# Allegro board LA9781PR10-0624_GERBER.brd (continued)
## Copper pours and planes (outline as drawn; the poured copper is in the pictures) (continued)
LX_CHG on BOTTOM (solid shape): 215.24,29.4 215.24,26.48 216.38,25.34 216.38,23.05 215.62,22.29 215.62,20.38 215.24,20 213.46,20 212.06,21.4 205.84,21.4 205.33,21.91 205.33,28.55 205.76,28.98 211.92,28.98 212.6,29.66 214.98,29.66
LX_CHG on BOTTOM (solid shape): 224.26,30.16 224.26,29.53 224.13,29.4 223.75,29.4 223.62,29.27 223.62,28.64 223.49,28.51 222.48,28.51 222.35,28.64 222.35,30.16 222.48,30.29 224.13,30.29
LX_CHG on IN2 (solid shape): 223.62,28.89 223.62,28.26 223.37,28 221.08,28 221.08,29.15 223.37,29.15
LX_CHG on IN2 (solid shape): 215.87,27.12 215.87,25.72 215.62,25.46 213.97,25.46 213.71,25.72 213.71,27.12 214.1,27.5 215.49,27.5
P1_SW on TOP (solid shape): 172.19,158.94 172.19,157.8 172.44,157.54 174.47,157.54 174.73,157.8 174.73,158.94 175.11,159.32 178.15,159.32 178.66,158.81 178.66,155.08 178.46,154.88 175.67,154.88 175.06,154.27 174.37,154.27 174.22,154.42 174.22,154.75 174.09,154.88 173.46,154.88 173.2,154.62 173.2,153.86 172.95,153.61 170.15,153.61 169.77,153.99 169.77,155.51 169.39,155.89 167.99,155.89 167.74,156.15 167.74,157.29 167.99,157.54 168.38,157.54 168.63,157.8 168.63,159.07 168.88,159.32 171.8,159.32
P2_SW on TOP (solid shape): 184.63,158.94 184.63,157.8 184.89,157.54 186.92,157.54 187.17,157.8 187.17,159.07 187.3,159.2 190.6,159.2 190.73,159.07 190.73,155.16 190.47,154.9 185.39,154.9 185.14,154.65 185.14,154.27 184.91,154.04 184.5,154.04 184.38,154.17 184.38,154.75 183.62,154.75 183.62,153.86 183.36,153.61 182.47,153.61 182.09,153.99 182.09,154.62 181.2,155.51 181.2,159.07 181.33,159.2 184.38,159.2
P2_SW on BOTTOM (solid shape): 187.81,158.69 187.81,157.8 187.68,157.67 186.66,157.67 186.54,157.54 186.54,156.91 186.41,156.78 186.03,156.78 185.9,156.91 185.9,158.05 185.97,158.19 185.97,158.35 185.97,158.37 186.41,158.81 187.68,158.81
P3_SW on TOP (solid shape): 198.73,158.81 198.73,157.42 198.98,157.16 201.01,157.16 201.27,157.42 201.27,158.81 201.4,158.94 204.57,158.94 204.82,158.69 204.82,154.24 204.19,153.61 196.95,153.61 196.7,153.86 196.7,154.83 196.49,155.03 194.97,155.03 194.79,154.85 194.79,153.86 194.54,153.61 193.9,153.61 193.65,153.86 193.65,154.75 192.76,154.75 192.76,153.86 192.51,153.61 191.74,153.61 191.49,153.86 191.49,156.91 191.87,157.29 194.92,157.29 195.17,157.54 195.17,158.69 195.43,158.94 198.6,158.94
P3_SW on BOTTOM (solid shape): 197.84,155.89 197.84,154.62 197.71,154.5 197.36,154.5 197.36,154.63 197.18,155.07 196.71,155.28 196.7,155.32 196.7,155.89 196.82,156.02 197.71,156.02
PBATT+ on TOP (solid shape): 189.46,15.69 189.46,6.54 189.2,6.29 185.41,6.29 185.16,6.53 185.16,10.72 185.38,10.94 186.4,10.94 187.04,11.58 187.04,12.64 186.92,12.76 185.01,12.76 184.76,13.02 184.76,15.94 185.01,16.19 188.95,16.19
PBATT+ on BOTTOM (solid shape): 192.63,15.43 192.63,11.49 190.98,9.84 186.28,9.84 185.77,10.35 185.77,13.78 186.28,14.29 187.3,14.29 187.55,14.03 188.06,14.03 188.31,14.29 188.31,15.56 188.82,16.07 192,16.07
PBATT+_C on TOP (solid shape): 193.78,10.61 193.78,9.72 193.52,9.46 193.52,8.02 193.48,7.93 193.39,7.92 192.94,7.76 193,7.29 193.14,7.14 193.14,6.92 193.27,6.8 193.27,3.58 193.22,3.57 192.41,2.65 193.22,1.73 193.27,1.72 193.27,1.59 193.01,1.33 188.57,1.33 188.19,1.72 188.19,4.26 190.22,6.29 190.22,10.61 190.6,10.99 193.39,10.99
PBATT+_C on BOTTOM (solid shape): 194.03,10.86 194.03,8.7 193.27,7.94 193.25,7.94 193,7.83 192.89,7.58 192.89,7.56 192.38,7.05 192.38,2.1 192,1.72 188.82,1.72 188.31,2.22 188.31,6.92 192.63,11.24 193.65,11.24
PBATT_IN_SS on BOTTOM (solid shape): 188.51,27.05 188.54,26.98 188.57,26.94 188.57,21.78 188.82,21.53 192.38,21.53 192.89,21.02 192.89,19.92 192.82,19.83 192.71,19.85 192.05,19.6 192.71,19.34 192.82,19.36 192.89,19.27 192.89,17.59 191.87,16.57 187.48,16.57 187.4,16.6 187.38,16.68 187.02,17.03 186.66,16.68 186.63,16.6 186.56,16.57 184.79,16.57 184.7,16.63 184.7,16.73 184.54,17.25 184.06,17 184.02,16.94 183.69,16.84 183.55,16.61 183.54,16.57 181.58,16.57 180.69,17.46 180.69,21.78 183.36,21.78 184.25,22.67 184.25,26.99 184.76,27.5 188.06,27.5
PHASE1 on TOP (solid shape): 168.38,165.8 168.38,163.77 168.12,163.51 167.49,163.51 167.23,163.77 167.23,165.8 167.36,165.93 168.25,165.93
PHASE1 on TOP (solid shape): 174.47,165.8 174.47,163.77 174.22,163.51 173.58,163.51 173.33,163.77 173.33,165.8 173.46,165.93 174.34,165.93
PHASE1 on TOP (solid shape): 155.85,167.17 155.85,166.18 156.11,165.93 156.11,164.96 156.36,164.71 156.74,164.71 156.84,164.61 156.84,163.87 156.69,163.72 155.88,163.72 155.73,163.87 155.73,164.71 155.57,164.86 155.57,165.73 155.58,165.79 155.58,165.85 155.57,165.88 155.65,165.95 155.65,167.17 155.68,167.2 155.83,167.2
PHASE1 on IN3 (solid shape): 174.47,165.93 174.47,164.66 174.22,164.4 172.57,164.4 172.31,164.66 172.31,165.8 172.57,166.05 174.34,166.05
PHASE1 on IN3 (solid shape): 168.5,165.93 168.5,163.77 168.12,163.39 167.36,163.39 167.11,163.64 167.11,164.66 166.98,164.78 165.71,164.78 165.33,165.16 165.33,165.93 165.45,166.05 168.38,166.05
PHASE1 on IN3 (solid shape): 156.13,166 156.13,165.96 156.13,165.95 156.11,165.82 156.13,165.69 156.13,165.69 156.13,165.33 156.13,165.32 156.11,165.19 156.13,165.06 156.13,165.05 156.13,164.91 156.44,164.61 156.44,163.97 156.26,163.79 155.83,163.79 155.57,164.05 155.57,165.73 155.58,165.8 155.57,165.87 155.57,166.03 155.62,166.08 156.06,166.08
PHASE2 on TOP (solid shape): 180.82,165.8 180.82,163.77 180.57,163.51 179.93,163.51 179.68,163.77 179.68,165.8 179.81,165.93 180.69,165.93
PHASE2 on TOP (solid shape): 186.92,165.8 186.92,163.77 186.66,163.51 186.03,163.51 185.77,163.77 185.77,165.8 185.9,165.93 186.79,165.93
PHASE2 on TOP (solid shape): 158.72,167.32 158.98,167.32 159.16,167.14 159.19,167.06 159.23,166.99 159.23,166.94 159.36,166.82 159.61,166.82 160.17,166.26 161.01,166.26 161.11,166.15 161.11,165.27 161.06,165.21 160.4,165.21 158.16,167.45 157.66,167.45 157.66,167.65 158.39,167.65
PHASE2 on IN3 (solid shape): 181.08,167.01 181.08,164.72 180.69,164.34 179.49,164.34 178.92,164.91 178.92,167.07 179.11,167.26 180.82,167.26
PHASE2 on IN3 (solid shape): 187.04,167.07 187.04,164.78 186.66,164.4 185.77,164.4 185.52,164.66 185.52,167.07 185.77,167.32 186.79,167.32
PHASE2 on IN3 (solid shape): 159.05,167.35 159.13,167.32 159.16,167.24 159.54,166.84 159.92,167.24 159.94,167.32 160.02,167.35 161.44,167.35 161.52,167.27 161.52,166.94 160.91,166.33 159.15,166.33 158.72,166.76 158.72,167.2 158.88,167.35
PHASE3 on TOP (solid shape): 194.79,164.28 194.79,163.39 194.66,163.26 193.39,163.26 193.27,163.39 193.27,164.4 193.39,164.53 194.54,164.53
PHASE3 on TOP (solid shape): 200.89,165.55 200.89,163.51 200.63,163.26 200,163.26 199.74,163.51 199.74,165.55 199.9,165.7 200.73,165.7
PHASE3 on TOP (solid shape): 199.67,172.82 199.67,172.38 199.71,172.34 199.71,172.31 200.35,172.31 200.47,172.2 200.47,170.13 200.39,170.05 200.21,170.05 200.14,169.98 199.15,169.98 198.92,170.21 198.92,171.48 198.36,172.03 198.36,172.77 198.49,172.9 199.59,172.9
PHASE3 on IN3 (solid shape): 195.55,164.4 195.55,163.26 195.17,162.88 193.52,162.88 193.14,163.26 193.14,164.53 193.39,164.78 195.17,164.78
PHASE3 on IN3 (solid shape): 201.5,172.07 201.5,170.07 201.4,169.96 200.56,169.96 199.88,170.64 199.88,172.11 200.23,172.45 201.12,172.45
PHASE3 on IN3 (solid shape): 201.4,165.93 201.4,163.64 201.01,163.26 200,163.26 199.62,163.64 199.62,165.93 200,166.31 201.01,166.31
SNB_CPU_P2 on BOTTOM (solid shape): 192.12,158.69 192.12,157.93 191.74,157.54 188.7,157.54 188.31,157.93 188.31,158.69 188.57,158.94 191.87,158.94
SNB_CPU_P3 on BOTTOM (solid shape): 197.84,159.32 197.84,156.66 197.71,156.53 196.7,156.53 196.57,156.66 196.57,159.32 196.7,159.45 197.71,159.45
SNUB_1.5VSP on BOTTOM (solid shape): 99.96,26.31 99.96,24.74 99.76,24.54 98.56,24.54 98.12,24.98 98.12,26.29 98.31,26.48 99.8,26.48
SNUB_1.35V on TOP (solid shape): 139.42,18.48 139.42,17.87 139.37,17.82 139.33,17.75 139.29,17.72 139.29,17.57 139.29,16.07 139.04,15.81 137.26,15.81 137.01,16.07 137.01,18.48 137.26,18.73 139.17,18.73
SNUB_3V on TOP (solid shape): 39.34,50.99 39.34,48.71 38.96,48.32 37.18,48.32 36.93,48.58 36.93,49.09 37.95,50.1 37.95,50.99 38.2,51.25 39.09,51.25
SNUB_5V on TOP (solid shape): 31.95,30.48 31.95,29.3 32.03,29.22 32.98,29.22 33.03,29.17 33.03,28.18 32.97,28.12 30.99,28.12 30.82,28.28 30.82,30.39 31.02,30.59 31.84,30.59
SNUB_CHG on BOTTOM (solid shape): 217.91,22.04 217.91,20.4 217.13,19.83 216.48,19.11 216.25,19.11 216,19.37 216,22.04 216.25,22.29 217.65,22.29
SW1 on TOP (solid shape): 34.44,27.99 34.44,26.5 34.29,26.36 33.45,26.36 33.03,25.94 33.03,25.53 32.94,25.45 31.16,25.45 30.21,26.39 30.21,27.63 30.52,27.93 33.12,27.93 33.34,28.14 34.29,28.14
SW1 on BOTTOM (solid shape): 37.35,31.14 37.35,28.93 36.71,28.3 36.71,26.22 36.29,25.79 31.21,25.79 31.12,25.69 30.88,25.69 30.77,25.81 30.49,25.81 30.14,26.16 30.14,27.12 29.7,27.55 28.78,27.55 28.52,27.8 28.52,30.11 28.83,30.42 32.62,30.42 32.63,30.41 34.56,30.41 34.9,30.75 34.9,31.19 34.94,31.23 37.26,31.23
SW2 on TOP (solid shape): 39.22,47.69 39.22,45.4 38.61,44.79 33.53,44.79 32.1,43.37 30.2,43.37 29.69,43.88 29.69,45.15 30.2,45.66 31.47,45.66 31.98,46.17 31.98,47.69 32.23,47.94 35.53,47.94 35.66,48.07 38.84,48.07
SW2 on BOTTOM (solid shape): 32.1,48.45 33.76,48.45 34.01,48.2 34.01,44.51 33.37,43.88 29.44,43.88 29.18,44.13 29.18,48.58 29.69,49.09 31.47,49.09
SW2 on BOTTOM (solid shape): 36.68,41.72 36.68,41.2 36.43,40.95 36.36,40.85 36.32,40.73 36.3,40.7 36.3,40.45 36.04,40.2 36.04,39.1 35.98,39.04 35.85,39.04 35.79,39.1 35.79,40.2 35.53,40.45 35.15,40.45 35.03,40.58 35.03,40.96 35.53,41.47 35.53,41.59 35.79,41.85 36.55,41.85
SW2 on IN1 (solid shape): 36.3,42.23 36.3,40.58 36.04,40.32 35.15,40.32 34.9,40.58 34.9,42.36 35.15,42.61 35.91,42.61
SW2 on IN1 (solid shape): 34.14,44.26 34.14,43.69 33.95,43.5 31.72,43.5 31.47,43.75 31.47,44.26 31.72,44.51 33.88,44.51
SW_1.35V on TOP (solid shape): 136.5,18.99 136.5,15.81 137.13,15.18 139.17,15.18 139.67,14.67 139.67,13.53 139.29,13.15 130.02,13.15 128.88,14.29 128.88,21.53 129.32,21.97 133.51,21.97
SW_1.35V on BOTTOM (solid shape): 148.91,21.72 148.91,21.49 148.82,21.4 148.82,20.89 148.06,20.13 148.06,18.86 147.93,18.73 147.17,18.73 147.04,18.86 147.04,20.51 147.97,21.44 147.97,21.72 148.03,21.78 148.84,21.78
SW_1.35V on BOTTOM (solid shape): 132.94,26.12 132.94,22.8 133.7,22.04 136.12,22.04 136.5,21.65 136.5,17.21 135.61,16.32 129.89,16.32 129.39,16.83 129.39,23.94 128.88,24.45 128.88,25.82 129.36,26.3 132.76,26.3
SW_1.35V on IN2 (solid shape): 146.57,21.49 146.57,21.48 146.64,21.38 146.74,21.31 146.75,21.31 147.04,21.02 148.06,21.02 148.31,20.77 148.31,20.26 148.06,20 146.53,20 142.09,24.45 133.07,24.45 131.42,22.8 131.42,21.65 131.16,21.4 130.28,21.4 130.15,21.53 130.15,22.92 132.69,25.46 142.59,25.46
SW_+1.05VSP on TOP (solid shape): 45.44,59.88 45.44,55.94 45.19,55.69 43.28,55.69 42.52,54.93 39.6,54.93 39.22,55.31 39.22,58.74 39.09,58.87 37.31,58.87 37.18,58.99 37.18,60.01 37.31,60.14 45.19,60.14
SW_+1.05VSP on BOTTOM (solid shape): 39.27,64.15 39.27,62.88 40.36,61.79 40.36,55.44 40.11,55.18 36.98,55.18 36.57,55.59 36.57,59.25 38.86,61.53 38.86,63.49 38.86,63.52 38.86,64.08 38.86,64.15 38.96,64.25 39.17,64.25
UG_3V on TOP (solid shape): 33.63,49.21 33.63,48.2 33.5,48.07 32.23,48.07 31.98,48.32 31.98,48.71 32.61,49.34 33.5,49.34
UG_3V on BOTTOM (solid shape): 37.82,40.58 37.82,39.94 36.9,39.03 36.61,39.03 36.57,39.07 36.57,39.84 36.93,40.2 36.93,40.32 36.98,40.35 37.02,40.39 37.39,40.75 37.64,40.75
UG_3V on IN1 (solid shape): 34.77,49.21 34.77,48.58 34.64,48.45 32.36,48.45 32.23,48.58 32.23,49.21 32.36,49.34 34.64,49.34
UG_3V on IN1 (solid shape): 37.95,41.47 37.95,40.07 37.44,39.56 36.8,39.56 36.55,39.82 36.55,41.59 36.68,41.72 37.69,41.72
UG_5V on TOP (solid shape): 34.4,26.07 34.4,25.25 34.28,25.12 33.3,25.12 33.18,25.24 33.18,25.79 33.55,26.15 34.33,26.15
UG_5V on BOTTOM (solid shape): 36.93,36.81 36.93,36.77 37.06,36.64 37.44,36.64 37.57,36.51 37.57,35.62 37.44,35.5 36.93,35.5 36.68,35.75 36.68,36.01 36.63,36.06 36.63,36.83 36.66,36.87 36.87,36.87
UG_5V on IN4 (solid shape): 35.11,26.52 35.11,25.38 34.86,25.12 33.34,25.12 33.08,25.38 33.08,26.52 33.34,26.77 34.86,26.77
UG_5V on IN4 (solid shape): 37.55,36.34 37.55,35.33 37.39,35.17 35.72,35.17 35.57,35.32 35.57,36.28 35.83,36.54 37.35,36.54
UG_+1.05VSP on TOP (solid shape): 37.06,61.02 37.06,60.59 37.06,60.06 37.06,60.06 37.06,59.12 36.8,58.87 36.42,58.87 36.04,59.25 36.04,60.64 36.55,61.15 36.93,61.15
UG_+1.05VSP on BOTTOM (solid shape): 38.73,64.18 38.73,61.58 37.03,59.88 36.42,59.88 36.04,60.26 36.04,60.64 38.45,63.06 38.45,64.17 38.51,64.22 38.68,64.22
UGATE1 on TOP (solid shape): 169.7,165.8 169.7,163.77 169.44,163.51 168.81,163.51 168.55,163.77 168.55,165.8 168.68,165.93 169.57,165.93
UGATE1 on TOP (solid shape): 175.79,165.8 175.79,163.77 175.54,163.51 174.9,163.51 174.65,163.77 174.65,165.8 174.78,165.93 175.66,165.93
UGATE1 on TOP (solid shape): 155.45,167.07 155.45,165.93 155.45,165.01 155.34,164.91 155.07,164.91 154.94,165.04 154.94,165.9 155.24,166.21 155.24,167.09 155.29,167.15 155.37,167.15
UGATE1 on IN1 (solid shape): 169.9,167.2 169.9,164.53 169.65,164.28 168.76,164.28 168.5,164.53 168.5,167.2 168.76,167.45 169.65,167.45
UGATE1 on IN1 (solid shape): 176,166.31 176,164.78 175.74,164.53 174.85,164.53 174.6,164.78 174.6,165.8 173.84,166.56 173.84,167.2 174.09,167.45 174.85,167.45
UGATE1 on IN2 (solid shape): 170.28,165.8 170.28,163.64 169.9,163.26 168.63,163.26 168.25,163.64 168.25,165.8 168.63,166.18 169.9,166.18
UGATE1 on IN2 (solid shape): 155.47,165.98 155.47,164.68 155.73,164.43 155.73,164 155.45,163.72 155.04,163.72 154.68,164.07 154.68,165.98 154.79,166.08 155.37,166.08
UGATE2 on TOP (solid shape): 182.14,165.8 182.14,163.77 181.89,163.51 181.25,163.51 181,163.77 181,165.8 181.13,165.93 182.01,165.93
UGATE2 on TOP (solid shape): 188.24,165.8 188.24,163.77 187.98,163.51 187.35,163.51 187.09,163.77 187.09,165.8 187.22,165.93 188.11,165.93
UGATE2 on TOP (solid shape): 159.28,167.91 159.32,167.83 159.37,167.76 159.87,167.27 159.87,167.07 159.74,166.94 159.49,166.94 159.36,167.07 159.36,167.12 159.2,167.29 159.03,167.45 158.98,167.45 158.93,167.5 158.82,167.5 158.47,167.86 157.68,167.86 157.68,168.06 158.49,168.06 158.52,168.09 159.1,168.09
UGATE2 on IN2 (solid shape): 182.73,166.75 182.73,164.59 182.35,164.21 181.08,164.21 180.69,164.59 180.69,166.75 181.08,167.13 182.35,167.13
UGATE2 on IN2 (solid shape): 161.01,168.34 161.01,167.2 160.76,166.94 159.49,166.94 159.29,167.14 159.28,167.15 159.2,167.29 159.06,167.38 159.05,167.38 158.85,167.58 158.8,167.58 158.72,167.65 158.72,168.49 158.82,168.59 160.76,168.59
UGATE2 on IN4 (solid shape): 182.6,166.56 182.6,164.66 182.22,164.28 181.2,164.28 180.82,164.66 180.82,166.56 181.08,166.82 182.35,166.82
UGATE2 on IN4 (solid shape): 188.44,166.69 188.44,164.66 188.19,164.4 187.17,164.4 186.92,164.66 186.92,166.69 187.17,166.94 188.19,166.94
UGATE3 on TOP (solid shape): 200.19,168.88 200.39,168.88 200.47,168.81 200.47,167.95 199.62,167.1 199.62,166.43 199.37,166.18 198.51,166.18 198.26,166.43 198.26,167.4 199.15,168.29 199.15,168.3 199.73,168.89 200.19,168.89
VLDOIN_1.35V on BOTTOM (solid shape): 147.8,23.25 147.8,23.19 147.97,23.03 148.82,23.03 148.88,22.96 148.88,22.78 148.84,22.75 147.9,22.75 147.6,23.05 146.15,23.05 146.1,23.1 146.1,23.58 145.54,23.58 145.54,23.79 146.1,23.79 146.1,24.19 146.12,24.22 146.84,24.22
N16751240 on TOP (solid shape): 9.75,66.87 9.75,63.82 9.63,63.69 8.99,63.69 8.86,63.82 8.86,64.14 8.89,64.16 9.09,64.48 8.89,64.8 8.86,64.81 8.86,66.87 8.99,66.99 9.63,66.99
N16855849 on TOP (solid shape): 156.89,163.08 156.89,162.55 156.72,162.37 155.43,162.37 155.42,162.37 155.29,162.4 155.17,162.37 155.16,162.37 154.89,162.37 154.77,162.42 154.64,162.42 154.62,162.41 154.51,162.52 154.51,163.11 154.66,163.26 156.72,163.26
N17657331 on TOP (solid shape): 178.03,28.89 178.03,26.61 174.73,23.31 173.58,23.31 172.31,22.04 172.31,19.24 171.8,18.73 170.41,18.73 170.03,18.35 170.03,17.72 169.65,17.34 168.25,17.34 167.87,17.72 167.87,20.89 168.12,21.15 169.9,21.15 170.15,21.4 170.15,22.16 172.22,24.23 172.31,24.25 172.39,24.19 172.87,23.96 173.11,24.44 173.12,24.53 173.2,24.58 174.47,24.58 175.46,25.57 175.56,25.57 175.56,25.67 176.76,26.86 176.76,27.88 176.5,28.13 174.6,28.13 174.34,28.39 174.34,29.27 174.6,29.53 177.39,29.53
N17657445 on TOP (solid shape): 192.25,21.4 192.25,20.13 192.63,19.75 192.63,11.75 192.25,11.37 190.09,11.37 189.84,11.62 189.84,15.94 189.2,16.57 189.2,21.4 189.46,21.65 192,21.65
N17707524 on BOTTOM (solid shape): 250.84,19.92 250.84,18.97 250.81,18.94 248.93,18.94 248.84,19.03 248.84,19.56 248.92,19.63 249.6,19.63 250,20.03 250.73,20.03
N17794318 on TOP (solid shape): 132.56,112.21 132.56,110.94 132.43,110.81 131.67,110.81 131.42,110.55 131.42,108.52 130.28,107.38 128.88,107.38 128.62,107.63 128.62,109.03 128.63,109.04 128.63,110.78 130.19,112.33 132.43,112.33
N18986737 on BOTTOM (solid shape): 222.22,30.16 222.22,27.37 222.1,27.24 221.46,27.24 221.33,27.37 221.33,30.16 221.46,30.29 222.1,30.29
N20013103 on TOP (solid shape): 52.03,43.26 52.03,40.73 51.61,40.31 50.02,40.31 49.87,40.46 49.87,41.03 50.32,41.48 50.87,41.48 51.14,41.75 51.14,43.45 51.19,43.5 51.79,43.5
N20194878 on BOTTOM (solid shape): 242.49,16.97 242.49,15.55 242.42,15.47 241.1,15.47 240.9,15.66 240.9,16.84 241.15,17.08 242.38,17.08
N23707366 on TOP (solid shape): 49.53,43.11 49.53,41.71 49.15,41.33 49.15,40.44 49.02,40.31 48.72,40.31 48.63,40.4 48.63,41.43 48.86,41.66 48.86,42.96 49.07,43.18 49.46,43.18
N25627554 on TOP (solid shape): 291.59,144.79 291.59,143.62 291.35,143.38 286.4,143.38 286.21,143.57 286.21,144.88 286.37,145.05 286.38,145.05 286.66,145.33 291.06,145.33
N48711348 on TOP (solid shape): 162.79,167.45 162.79,165.29 162.66,165.16 161.77,165.16 161.64,165.29 161.64,167.45 161.77,167.58 162.66,167.58
N51302473 on TOP (solid shape): 202.98,172.95 202.98,171.73 202.77,171.51 201.65,171.51 201.47,171.34 201.47,170.08 201.42,170.03 200.68,170.03 200.62,170.09 200.62,173.05 200.68,173.11 202.82,173.11
N85751870 on TOP (solid shape): 41.93,61.34 41.93,60.81 41.52,60.39 37.44,60.39 37.18,60.64 37.18,61.41 37.44,61.66 41.62,61.66
N85751893 on TOP (solid shape): 44.68,54.8 45.31,54.8 45.44,54.67 45.44,52.9 45.19,52.64 44.68,52.64 44.42,52.9 44.42,53.4 44.17,53.66 43.53,53.66 43.41,53.79 43.41,54.8 43.53,54.93 44.55,54.93

Small or netless copper shapes (teardrops, artwork), in the pictures only: 31 on TOP, 90 on BOTTOM, 22 on IN2, 16 on IN4

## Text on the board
User.Comments: LA-9781P | 2013-06-24 | 2014-06-24 | Amanda_shi | VAR10 | 1.0(A00) | +5V_RUN | +3.3V_RUN | +1.05V_M | +1.05V_RUN | +VCC_SA | +VCC_CORE | +VCC_GFXCORE | +5V_ALW | +DOCK_PWR_BAR | +PWR_SRC | GND | +1.5V_MEM | +3.3V_ALW | +1.05V_RUN_VTT
Ref Des/Silkscreen Top: LVDS | H2 | H26 | MXM    CARD | H27 | H7 | H28 | 1 | 2 | 3 | 2ND HDD | MAIN  HDD
DEVICE_TYPE_BOTTOM: 119.50 | 109.84 | 106.55 | 95.35 | 93.10 | 71.07 | 45.79 | 24.55 | 166.73 | 0.90 | 7.20 | 0.00 | 38.30 | 87.98 | 28.48 | 148.20 | 108.52 | 153.20 | 169.97 | 179.72 | 137.32 | 108.91 | 85.82 | 0.49 | 164.17 | 161.21 | 154.85 | 134.47 | 114.13 | 97.07 | 30.25 | 25.13 | 15.38 | 98.21 | 59.29 | 96.93 | 60.72 | 46.52 | 8.75 | 8.21 | 97.41 | 4.78 | 66.05 | 76.72 | 83.92 | 160.33
USER_PART_NUM_TOP: 113.02 | 91.15 | 80.02 | 64.71 | 54.52 | 50.37 | 43.20 | 146.22 | 114.35 | 111.57 | 108.55 | 110.77 | 65.35 | 156.47 | 60.72 | 46.52 | 13.30 | 0.90 | 142.30 | 104.30 | 74.13 | 72.20 | 56.20 | 149.90 | 41.55 | 11.75 | 0.00 | 102.49 | 137.07 | 152.30 | 72.15 | 58.27 | 28.17 | 2.78
COMPVAL_TYPE_BOTTOM: 119.80 | {\Fgdt;n}\Ftxt;3.80 | {\Fgdt;n}\Ftxt;7.00 | 7.50 | 8.50 | 53.80 | 50.20 | {\Fgdt;n}\Ftxt;3.00 | {\Fgdt;n}\Ftxt;6.00 | 160.27 | 18.45 | 11.40 | {\Fgdt;n}\Ftxt;1.20 | 3.40 | {\Fgdt;n}\Ftxt;8.50 | 10.45 | {\Fgdt;n}\Ftxt;4.00 | 13.30 | 69.77 | 0.00 | 18.40 | 28.38 | {\Fgdt;n}\Ftxt;5.20 | {\Fgdt;n}\Ftxt;4.20 | 137.56 | 72.00 | 85.12 | 87.51 | {\Fgdt;n}\Ftxt;8.00 | {\Fgdt;n}\Ftxt;3.60 | 134.08 | 8.67 | 170.00 | 173.20 | R3.25 | 162.27 | 151.77 | 79.70 | 70.37 | 0.40 | 13.00 | 12.00 | 154.77 | 68.47 | 24.77 | 8.77 | {\Fgdt;n}\Ftxt;6.50 | 92.80 | 89.60 | 74.90 | 150.47 | 47.35 | 4.80 | 10.60 | 21.30 | 15.60 | 14.60 | 7.40 | 5.80 | 138.57 | 96.77 | 26.40 | 161.77 | 23.60 | 13.60 | 18.60 | 92.14 | 83.07 | 70.10 | 75.10 | 80.10 | 92.20 | 97.20 | 74.70 | 143.60 | 147.60 | 151.10 | 3.17 | 163.00 | 166.60 | 173.80
PAGE_OUTLINE: 3.00 | {\Fgdt;n}\Ftxt;8.00 | 11.00 | R4.25 | 2.52 | 99.20 | {\Fgdt;n}\Ftxt;6.00 | 162.70 | 15.50 | 2.90 | R4.00 | 105.09 | R5.00 | 0.00 | 60.37 | 2.89 | 87.69 | 85.27 | 131.95
User.9: Printing White
User.10: Printing White
User.11: 123.29 | 122.79 | 0.00 | 91.05 | 169.77 | 159.50 | 182.56 | 7.23 | 166.27 | 171.77 | 96.52 | 85.02 | 48.77 | 7.43 | 56.76 | 90.30 | 180.56
User.12: 119.50 | 109.84 | 106.55 | 95.35 | 93.10 | 71.07 | 45.79 | 24.55 | 166.73 | 0.90 | 0.00 | 38.30 | 87.98 | 28.48 | 108.52 | 153.20 | 169.97 | 179.72 | 137.32 | 108.91 | 85.82 | 0.49 | 164.17 | 161.21 | 154.85 | 148.20 | 134.47 | 114.13 | 97.07 | 30.25 | 25.13 | 15.38 | 98.21 | 59.29 | 96.93 | 60.72 | 46.52 | 8.75 | 8.21 | 97.41 | 4.78 | 66.05 | 76.72 | 83.92 | 160.33
User.14: 119.80 | {\Fgdt;n}\Ftxt;3.80 | {\Fgdt;n}\Ftxt;7.00 | 7.50 | 8.50 | 53.80 | 50.20 | {\Fgdt;n}\Ftxt;3.00 | {\Fgdt;n}\Ftxt;6.00 | 160.27 | 18.45 | 11.40 | {\Fgdt;n}\Ftxt;1.20 | 3.40 | {\Fgdt;n}\Ftxt;8.50 | {\Fgdt;n}\Ftxt;4.00 | 69.77 | 0.00 | 18.40 | 28.38 | {\Fgdt;n}\Ftxt;5.20 | {\Fgdt;n}\Ftxt;4.20 | 137.56 | 72.00 | 85.12 | 87.51 | {\Fgdt;n}\Ftxt;8.00 | {\Fgdt;n}\Ftxt;3.60 | 134.08 | 8.67 | 170.00 | 173.20 | R3.25 | 162.27 | 151.77 | 79.70 | 70.37 | 0.40 | 13.00 | 12.00 | 4.00 | 3.60 | 4.60 | 154.77 | 68.47 | 24.77 | 8.77 | {\Fgdt;n}\Ftxt;6.50 | 92.80 | 89.60 | 74.90 | 150.47 | 47.35 | 4.80 | 10.60 | 21.30 | 15.60 | 14.60 | 7.40 | 5.80 | 138.57 | 96.77 | 26.40 | 161.77 | 23.60 | 13.60 | 18.60 | 92.14 | 83.07 | 70.10 | 75.10 | 80.10 | 92.20 | 97.20 | 74.70 | 143.60 | 147.60 | 151.10 | 3.17 | 163.00 | 166.60 | 173.80 | 3.00
User.15: Printing White
User.16: 113.02 | 91.15 | 80.02 | 64.71 | 54.52 | 50.37 | 43.20 | 146.22 | 114.35 | 111.57 | 108.55 | 110.77 | 65.35 | 156.47 | 60.72 | 46.52 | 13.30 | 0.90 | 142.30 | 104.30 | 74.13 | 72.20 | 56.20 | 149.90 | 41.55 | 11.75 | 0.00 | 102.49 | 137.07 | 152.30 | 72.15 | 58.27 | 28.17 | 2.78
User.18: 3.00 | {\Fgdt;n}\Ftxt;8.00 | 11.00 | R4.25 | 2.52 | 99.20 | {\Fgdt;n}\Ftxt;6.00 | 162.70 | 15.50 | 2.90 | R4.00 | 105.09 | R5.00 | 0.00 | 60.37 | 2.89 | 87.69 | 85.27 | 131.95
User.19: Printing White
User.20: 123.29 | 122.79 | 0.00 | 91.05 | 169.77 | 159.50 | 182.56 | 7.23 | 166.27 | 171.77 | 96.52 | 85.02 | 48.77 | 7.43 | 56.76 | 90.30 | 180.56
User.40: Width/space | 8.2 | 7 | 5.5 | 5.8 | 4.3 | 5 | 4 | 5.8 / 4.2 | 5 / 4 | 5.5 / 4.5 | 5.3 / 4.7 | 4.3 / 4 | 4.6 / 4.7 | 4 / 4.5 | 5 / 4.8 | 4.3 / 4.8 | 4 / 5.1 | 7.5 / 5.5 | 8 / 5.5 | 4 / 6.5 | 5 / 7 | 4.5 / 10 | 3.5 / 10 | L1-TOP | L2-GND1 | L3-IN1 | L4-VCC | L5-IN2 | L6-IN3 | L7-GND2 | L8-IN4 | L9-GND3 | L10-BOT | LAYER | NAME | L5/L7 | Ref | 100ohm | no ref
User.41: FIGURE | SIZE | 8.0 | 10.0 | 20.0 | 22.0 | 24.0 | 30.0 | 31.0 | 35.0 | 36.0 | 39.0 | 47.0 | 55.0 | 118.0 | 142.0 | 150.0 | 165.0 | 40.0 | 43.0 | 63.0 | 65.0 | 67.0 | 39.0x33.0 | 45.0x37.0 | 55.0x31.0 | 59.0x31.0 | 63.0x24.0 | 75.0x24.0 | 75.0x37.0 | 83.0x39.0 | 94.0x24.0 | 94.0x31.0 | 94.0x39.0 | 96.0x39.0 | 102.0x31.0 | 112.0x39.0 | 118.0x33.0 | 120.0x39.0 | 142.0x118.0 | 472.0x295.0 | 67.0x43.0 | DRILL CHART: TOP to BOTTOM | ALL UNITS ARE IN MILS | PLATED | NON-PLATED | QTY | 4217 | 1 | 3577 | 20 | 19 | 15 | 7 | 18 | 8 | 4 | 16 | 3 | 2 | 13 | 9 | 10
